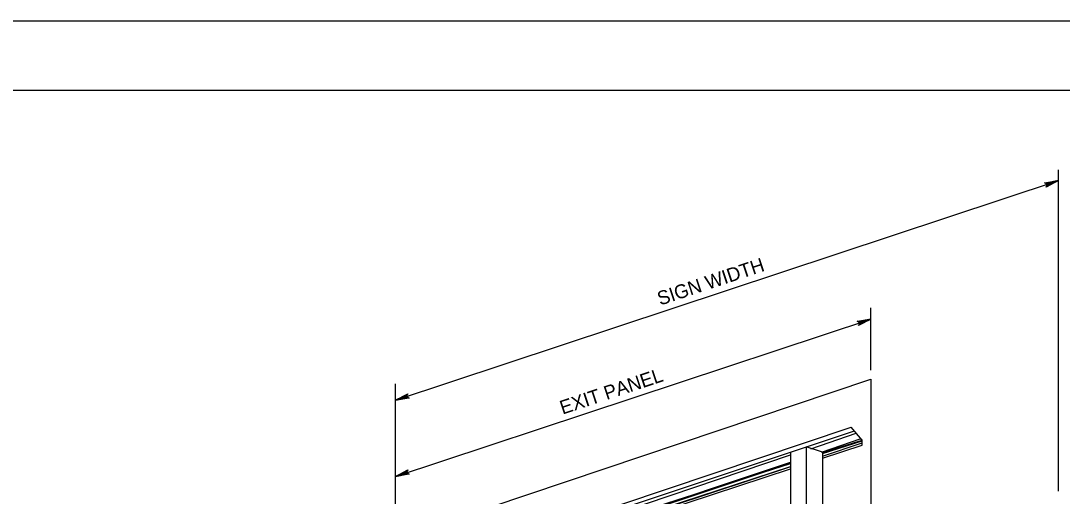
# Model space of a CAD drawing. Extents: x 650495 to 652241, y 298458 to 299646.
# Drawn here: x 650724.3 to 650949.7, y 299542.7 to 299645.6 of the extents above; entities that cross this region are included whole.
import ezdxf

# ---------------------------------------------------------------- set-up
doc = ezdxf.new("R2010")
doc.units = 0
for name, color, linetype in [('1', 7, 'Continuous'), ('2', 7, 'Continuous'), ('3', 7, 'Continuous'), ('PLT-BNDY', 7, 'Continuous')]:
    doc.layers.add(name, color=color, linetype=linetype)

# ---------------------------------------------------------------- blocks, each defined once
blk = doc.blocks.new('RARROW')
at = {"layer": '3'}
blk.add_lwpolyline([(-2.2695, 0.285), (-2.184875, 0.12075), (0, 0), (-2.2695, 0.285), (-2.38575, 0.384625), (0, 0), (-2.183125, -0.108), (-2.262875, -0.2705), (0, 0), (-2.38575, -0.379125), (-2.262875, -0.2705)], dxfattribs=at)

msp = doc.modelspace()

# ---------------------------------------------------------------- linework, layer by layer
at = {"layer": '1'}
msp.add_line((650535.31, 299630.63), (651321.31, 299630.63), dxfattribs=at)
at = {"layer": '2'}
for p, q in [((650948.9, 299543.77), (650948.9, 299613.37)), ((650805.4, 299563.47), (650948.9, 299611.07)), ((650908.3, 299569.97), (650908.3, 299583.47)), ((650805.4, 299546.97), (650908.3, 299581.07)), ((650908.3, 299581.07), (650908.3, 299581.07)), ((650805.4, 299533.47), (650908.3, 299568.07)), ((650805.4, 299535.47), (650805.4, 299567.07)), ((650908.3, 299568.07), (650908.3, 299528.47)), ((650809.3, 299525.87), (650904, 299557.67)), ((650904.7, 299556.77), (650832.8, 299532.87)), ((650895.3, 299552.97), (650905.1, 299556.37)), ((650906.4, 299554.87), (650904, 299557.67)), ((650894.3, 299553.37), (650894.3, 299483.87)), ((650897.8, 299552.27), (650894.3, 299553.37)), ((650897.6, 299552.27), (650906.2, 299555.17)), ((650897.8, 299552.17), (650906.4, 299554.87)), ((650897.8, 299551.97), (650906.4, 299554.67)), ((650897.8, 299551.37), (650906.4, 299554.27)), ((650897.8, 299550.97), (650906.4, 299553.77)), ((650906.4, 299553.77), (650906.4, 299554.97)), ((650832.8, 299532.07), (650890.9, 299551.67)), ((650890.9, 299552.27), (650890.9, 299482.47)), ((650897.8, 299552.27), (650897.8, 299482.67)), ((650833.9, 299531.57), (650890.9, 299549.77)), ((650834.4, 299531.27), (650890.9, 299550.07)), ((650834.7, 299531.17), (650890.9, 299549.87)), ((650837.1, 299531.57), (650890.9, 299549.17)), ((650837.1, 299531.37), (650891, 299549.17)), ((650837.1, 299530.97), (650890.9, 299548.67))]:
    msp.add_line(p, q, dxfattribs=at)
at = {"layer": 'PLT-BNDY'}
msp.add_lwpolyline([(650495.31, 299645.63), (651336.31, 299645.63), (651336.31, 299051.63), (650495.31, 299051.63)], close=True, dxfattribs=at)

# ---------------------------------------------------------------- block references
at = {"layer": '2'}
for p, xscale, yscale, rotation in [((650948.9, 299611.07), 1.2574347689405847, 1.3092961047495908, 18.89752500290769), ((650908.3, 299581.07), 1.2574347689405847, 1.3092961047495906, 18.36633733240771), ((650805.4, 299563.47), 1.2574347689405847, 1.3092961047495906, -161.6232987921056), ((650805.4, 299546.97), 1.2574347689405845, 1.3092961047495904, -161.19583579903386)]:
    msp.add_blockref('RARROW', p, dxfattribs=dict(at, xscale=xscale, yscale=yscale, rotation=rotation))

# ---------------------------------------------------------------- texts
for s, p in [('SIGN WIDTH', (650862.67, 299583.96)), ('EXIT PANEL', (650841.57, 299560.36))]:
    msp.add_text(s, height=3, rotation=18.3431, dxfattribs=at).set_placement(p)

doc.saveas('drawing.dxf')
